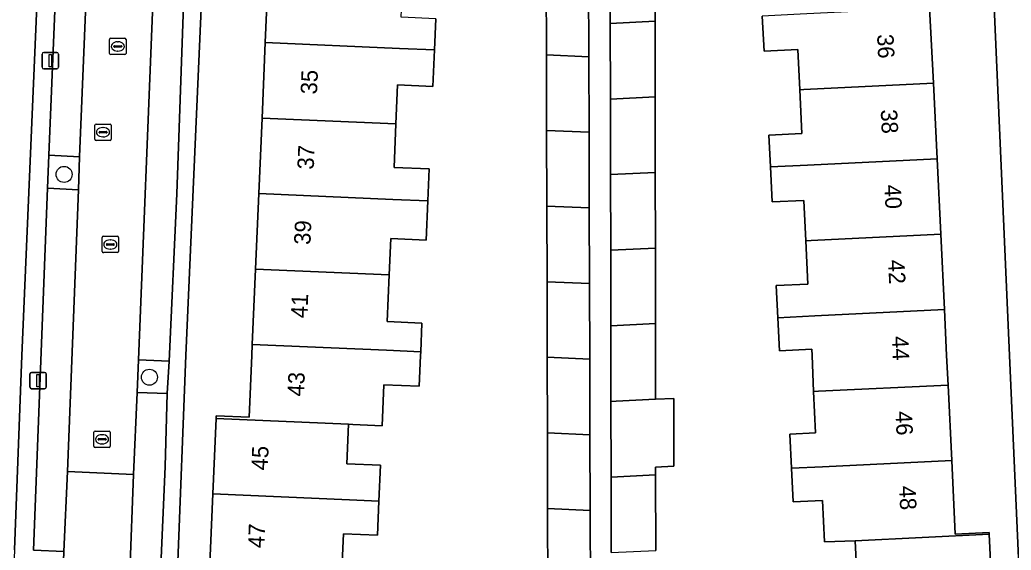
# Model space of a CAD drawing. Extents: x 162250 to 162661, y 380743 to 381606.
# Drawn here: x 162336.5 to 162396.8, y 380988.1 to 381020.5 of the extents above; entities that cross this region are included whole.
import ezdxf

# ---------------------------------------------------------------- set-up
doc = ezdxf.new("R2010")
doc.units = 0
for name, color, linetype in [('IMGEO_Boom', 7, 'Continuous'), ('IMGEO_Erf', 7, 'Continuous'), ('IMGEO_Groenvoorziening', 7, 'Continuous'), ('IMGEO_Kolk', 7, 'Continuous'), ('IMGEO_Lichtmast', 7, 'Continuous'), ('IMGEO_Pand', 7, 'Continuous'), ('IMGEO_Pand_nummerreeks', 7, 'Continuous'), ('IMGEO_Parkeervlak_open', 7, 'Continuous'), ('IMGEO_Rijbaan_lokaal_open', 7, 'Continuous'), ('IMGEO_Rioolput', 7, 'Continuous'), ('IMGEO_Voetpad_open', 7, 'Continuous')]:
    doc.layers.add(name, color=color, linetype=linetype)

msp = doc.modelspace()

# ---------------------------------------------------------------- linework, layer by layer
at = {"layer": 'IMGEO_Boom'}
for centre in [(162339.168, 381011.047), (162344.364, 380998.683)]:
    msp.add_circle(centre, 0.489, dxfattribs=at)
at = {"layer": 'IMGEO_Erf'}
for points in [[(162350.924, 381073.314), (162350.066, 381051.483), (162348.851, 381051.523), (162346.572, 381000), (162346.066, 380986.918)], [(162375.1, 381066.47), (162375.106, 381061.862), (162375.111, 381057.252), (162375.117, 381052.644), (162375.122, 381048.035), (162375.128, 381043.426), (162375.133, 381038.818), (162375.139, 381034.209), (162375.144, 381029.599), (162375.15, 381024.991), (162375.156, 381020.382), (162375.161, 381015.773), (162375.167, 381011.165), (162375.172, 381006.556), (162375.178, 381001.947), (162375.183, 380997.338), (162376.302, 380997.392), (162376.307, 380993.255), (162375.188, 380993.2), (162375.189, 380992.729), (162375.194, 380988.122)], [(162348.014, 380986.843), (162348.219, 380991.564), (162348.419, 380996.164), (162348.426, 380996.325), (162350.428, 380996.238), (162350.591, 381000), (162350.62, 381000.678), (162350.82, 381005.278), (162351.02, 381009.879), (162351.22, 381014.48), (162351.42, 381019.08), (162351.62, 381023.681), (162351.82, 381028.281), (162352.02, 381032.882), (162352.22, 381037.482), (162352.419, 381042.083), (162352.619, 381046.684), (162352.819, 381051.284), (162353.019, 381055.885), (162353.219, 381060.485), (162353.419, 381065.086)], [(162368.623, 380985.801), (162368.611, 380990.677), (162368.598, 380995.286), (162368.586, 380999.897), (162368.574, 381004.506), (162368.562, 381009.117), (162368.55, 381013.728), (162368.538, 381018.336), (162368.526, 381022.946), (162368.513, 381027.555), (162368.501, 381032.165), (162368.489, 381036.777), (162368.477, 381041.385), (162368.465, 381045.995), (162368.453, 381050.604), (162368.441, 381055.215), (162368.429, 381059.823), (162368.416, 381064.434)], [(162389.86, 381062.581), (162390.084, 381057.982), (162390.308, 381053.384), (162390.532, 381048.786), (162390.756, 381044.188), (162390.98, 381039.59), (162391.204, 381034.992), (162391.428, 381030.393), (162391.652, 381025.795), (162391.876, 381021.197), (162392.1, 381016.599), (162392.324, 381012.001), (162392.548, 381007.403), (162392.772, 381002.804), (162392.909, 381000), (162392.996, 380998.206), (162393.22, 380993.608), (162393.439, 380989.11), (162395.493, 380989.21), (162395.498, 380989.11), (162395.722, 380984.512)], [(162397.638, 380979.87), (162396.746, 381000), (162395.762, 381022.213), (162394.094, 381022.237), (162392.384, 381062.316)], [(162336.141, 380988.151), (162336.6, 381000), (162337.62, 381024.184), (162335.584, 381024.354)], [(162387.459, 380986.251), (162387.339, 380988.713), (162385.473, 380988.64), (162385.35, 380991.169), (162383.56, 380991.082), (162383.46, 380993.132), (162383.359, 380995.21), (162384.919, 380995.288), (162384.812, 380997.807), (162384.719, 381000), (162384.703, 381000.386), (162382.733, 381000.29), (162382.634, 381002.31), (162382.539, 381004.263), (162384.467, 381004.357), (162384.338, 381007.003), (162384.218, 381009.463), (162382.282, 381009.369), (162382.178, 381011.507), (162382.084, 381013.436), (162384.092, 381013.534), (162383.962, 381016.202), (162383.842, 381018.661), (162381.789, 381018.56), (162381.685, 381020.7)], [(162361.803, 381020.537), (162361.72, 381018.632), (162361.624, 381016.406), (162359.476, 381016.499), (162359.373, 381014.126), (162359.257, 381011.47), (162361.402, 381011.377), (162361.317, 381009.432), (162361.213, 381007.041), (162359.054, 381007.135), (162358.958, 381004.924), (162358.834, 381002.071), (162360.961, 381001.979), (162360.885, 381000.232), (162360.875, 381000), (162360.794, 380998.132), (162358.642, 380998.225), (162358.533, 380995.724), (162356.741, 380995.802), (162356.49, 380995.813), (162356.385, 380993.407), (162358.43, 380993.318), (162358.335, 380991.124), (162358.245, 380989.047), (162356.178, 380989.137), (162356.063, 380986.493)]]:
    msp.add_lwpolyline(points, dxfattribs=at)
at = {"layer": 'IMGEO_Groenvoorziening'}
for points in [[(162338.156, 381010.198), (162340.038, 381010.111), (162340.104, 381012.126), (162338.237, 381012.212)], [(162345.558, 380999.659), (162343.705, 380999.732), (162343.619, 380997.747), (162345.435, 380997.681)]]:
    msp.add_lwpolyline(points, close=True, dxfattribs=at)
at = {"layer": 'IMGEO_Kolk'}
for p, q in [((162341.937, 381018.422), (162341.937, 381019.274)), ((162342.012, 381019.348), (162342.864, 381019.348)), ((162342.196, 381018.842), (162342.196, 381018.854)), ((162342.239, 381018.891), (162342.637, 381018.891)), ((162342.425, 381019.128), (162342.45, 381019.128)), ((162342.68, 381018.854), (162342.68, 381018.842)), ((162342.938, 381019.274), (162342.938, 381018.422)), ((162342.864, 381018.348), (162342.012, 381018.348)), ((162342.634, 381018.805), (162342.236, 381018.805)), ((162342.448, 381018.568), (162342.423, 381018.568)), ((162341.483, 381006.349), (162341.483, 381007.201)), ((162341.558, 381007.275), (162342.41, 381007.275)), ((162341.742, 381006.769), (162341.742, 381006.781)), ((162341.785, 381006.818), (162342.183, 381006.818)), ((162341.971, 381007.055), (162341.996, 381007.055)), ((162342.226, 381006.781), (162342.226, 381006.769)), ((162342.484, 381007.201), (162342.484, 381006.349)), ((162342.41, 381006.275), (162341.558, 381006.275)), ((162342.18, 381006.732), (162341.782, 381006.732)), ((162341.994, 381006.495), (162341.969, 381006.495)), ((162340.978, 380994.473), (162340.978, 380995.325)), ((162341.053, 380995.399), (162341.905, 380995.399)), ((162341.979, 380995.325), (162341.979, 380994.473)), ((162341.237, 380994.893), (162341.237, 380994.905)), ((162341.675, 380994.856), (162341.277, 380994.856)), ((162341.28, 380994.942), (162341.678, 380994.942)), ((162341.466, 380995.179), (162341.491, 380995.179)), ((162341.721, 380994.905), (162341.721, 380994.893)), ((162341.905, 380994.399), (162341.053, 380994.399)), ((162341.489, 380994.619), (162341.464, 380994.619))]:
    msp.add_line(p, q, dxfattribs=at)
for points in [[(162341.937, 381018.422), (162341.937, 381019.274)], [(162342.012, 381019.348), (162342.864, 381019.348)], [(162342.938, 381019.274), (162342.938, 381018.422)], [(162342.864, 381018.348), (162342.012, 381018.348)], [(162341.483, 381006.349), (162341.483, 381007.201)], [(162341.558, 381007.275), (162342.41, 381007.275)], [(162342.484, 381007.201), (162342.484, 381006.349)], [(162342.41, 381006.275), (162341.558, 381006.275)], [(162340.978, 380994.473), (162340.978, 380995.325)], [(162341.053, 380995.399), (162341.905, 380995.399)], [(162341.979, 380995.325), (162341.979, 380994.473)], [(162341.905, 380994.399), (162341.053, 380994.399)]]:
    msp.add_lwpolyline(points, dxfattribs=at)
for centre, radius, start, end in [((162342.014, 381019.272), 0.0765, 91.55205, 178.44795), ((162342.014, 381019.272), 0.0765, 91.55205, 178.44795), ((162342.236, 381018.851), 0.0403, 85.87752, 175.75265), ((162342.233, 381018.841), 0.0366, 178.93798, 274.71019), ((162342.637, 381018.848), 0.043, 264.86636, 352.45326), ((162342.641, 381018.853), 0.0386, 1.73085, 96.63898), ((162342.862, 381019.272), 0.0765, 1.55205, 88.44795), ((162342.862, 381019.272), 0.0765, 1.55205, 88.44795), ((162342.014, 381018.424), 0.0765, 181.55205, 268.44795), ((162342.014, 381018.424), 0.0765, 181.55205, 268.44795), ((162342.862, 381018.424), 0.0765, 271.55205, 358.44795), ((162342.862, 381018.424), 0.0765, 271.55205, 358.44795), ((162341.56, 381007.199), 0.0765, 91.55205, 178.44795), ((162341.56, 381007.199), 0.0765, 91.55205, 178.44795), ((162341.782, 381006.778), 0.0403, 85.87752, 175.75265), ((162341.779, 381006.768), 0.0366, 178.93798, 274.71019), ((162342.183, 381006.775), 0.043, 264.86636, 352.45326), ((162342.187, 381006.78), 0.0386, 1.73085, 96.63898), ((162342.408, 381007.199), 0.0765, 1.55205, 88.44795), ((162342.408, 381007.199), 0.0765, 1.55205, 88.44795), ((162341.56, 381006.351), 0.0765, 181.55205, 268.44795), ((162341.56, 381006.351), 0.0765, 181.55205, 268.44795), ((162342.408, 381006.351), 0.0765, 271.55205, 358.44795), ((162342.408, 381006.351), 0.0765, 271.55205, 358.44795), ((162341.055, 380995.323), 0.0765, 91.55205, 178.44795), ((162341.055, 380995.323), 0.0765, 91.55205, 178.44795), ((162341.903, 380995.323), 0.0765, 1.55205, 88.44795), ((162341.903, 380995.323), 0.0765, 1.55205, 88.44795), ((162341.277, 380994.902), 0.0403, 85.87752, 175.75265), ((162341.274, 380994.892), 0.0366, 178.93798, 274.71019), ((162341.678, 380994.899), 0.043, 264.86636, 352.45326), ((162341.682, 380994.904), 0.0386, 1.73085, 96.63898), ((162341.055, 380994.475), 0.0765, 181.55205, 268.44795), ((162341.055, 380994.475), 0.0765, 181.55205, 268.44795), ((162341.903, 380994.475), 0.0765, 271.55205, 358.44795), ((162341.903, 380994.475), 0.0765, 271.55205, 358.44795)]:
    msp.add_arc(centre, radius, start, end, dxfattribs=at)
for centre, major_axis, ratio, start_param, end_param in [((162342.424, 381018.848), (-0.387, 0.002), 0.722429, 4.712389, 7.853982), ((162342.449, 381018.848), (-0.39, 0.002), 0.717154, 1.570796, 4.712389), ((162341.97, 381006.775), (-0.387, 0.002), 0.722429, 4.712389, 7.853982), ((162341.995, 381006.775), (-0.39, 0.002), 0.717154, 1.570796, 4.712389), ((162341.465, 380994.899), (-0.387, 0.002), 0.722429, 4.712389, 7.853982), ((162341.49, 380994.899), (-0.39, 0.002), 0.717154, 1.570796, 4.712389)]:
    msp.add_ellipse(centre, major_axis=major_axis, ratio=ratio, start_param=start_param, end_param=end_param, dxfattribs=at)
at = {"layer": 'IMGEO_Lichtmast'}
for p, q in [((162337.83, 381017.579), (162337.83, 381018.379)), ((162337.83, 381018.379), (162337.83, 381017.579)), ((162337.93, 381018.479), (162338.72, 381018.479)), ((162338.72, 381018.479), (162337.93, 381018.479)), ((162338.82, 381018.379), (162338.82, 381017.579)), ((162338.82, 381017.579), (162338.82, 381018.379)), ((162338.72, 381017.479), (162337.93, 381017.479)), ((162337.93, 381017.479), (162338.72, 381017.479)), ((162337.186, 380998.978), (162337.976, 380998.978)), ((162337.976, 380998.978), (162337.186, 380998.978)), ((162337.086, 380998.078), (162337.086, 380998.878)), ((162337.086, 380998.878), (162337.086, 380998.078)), ((162338.076, 380998.878), (162338.076, 380998.078)), ((162338.076, 380998.078), (162338.076, 380998.878)), ((162337.976, 380997.978), (162337.186, 380997.978)), ((162337.186, 380997.978), (162337.976, 380997.978))]:
    msp.add_line(p, q, dxfattribs=at)
for points in [[(162338.25, 381018.354), (162338.4, 381018.354), (162338.4, 381017.604), (162338.25, 381017.604), (162338.25, 381018.354)], [(162337.506, 380998.853), (162337.656, 380998.853), (162337.656, 380998.103), (162337.506, 380998.103), (162337.506, 380998.853)]]:
    msp.add_lwpolyline(points, dxfattribs=at)
for centre, start, end in [((162337.93, 381018.379), 90, 180), ((162337.93, 381018.379), 90, 180), ((162338.72, 381018.379), 0, 90), ((162338.72, 381018.379), 360, 90), ((162337.93, 381017.579), 180, 270), ((162337.93, 381017.579), 180, 270), ((162338.72, 381017.579), 270, 0), ((162338.72, 381017.579), 270, 0), ((162337.186, 380998.878), 90, 180), ((162337.186, 380998.878), 90, 180), ((162337.976, 380998.878), 0, 90), ((162337.976, 380998.878), 360, 90), ((162337.186, 380998.078), 180, 270), ((162337.186, 380998.078), 180, 270), ((162337.976, 380998.078), 270, 0), ((162337.976, 380998.078), 270, 0)]:
    msp.add_arc(centre, 0.1, start, end, dxfattribs=at)
at = {"layer": 'IMGEO_Pand'}
for points in [[(162372.421, 381024.858), (162372.429, 381020.249), (162375.156, 381020.382), (162375.15, 381024.991)], [(162359.808, 381023.325), (162351.62, 381023.681), (162351.42, 381019.08), (162359.589, 381018.725), (162361.72, 381018.632), (162361.803, 381020.537), (162359.691, 381020.629)], [(162371.111, 381022.833), (162368.526, 381022.946), (162368.538, 381018.336), (162371.124, 381018.223)], [(162383.962, 381016.202), (162384.222, 381016.215), (162392.1, 381016.599), (162391.876, 381021.197), (162383.998, 381020.813), (162381.685, 381020.7), (162381.789, 381018.56), (162383.842, 381018.661)], [(162372.436, 381015.641), (162375.161, 381015.773), (162375.156, 381020.382), (162372.429, 381020.249)], [(162361.72, 381018.632), (162359.589, 381018.725), (162351.42, 381019.08), (162351.22, 381014.48), (162359.373, 381014.126), (162359.476, 381016.499), (162361.624, 381016.406)], [(162371.124, 381018.223), (162368.538, 381018.336), (162368.55, 381013.728), (162371.137, 381013.616)], [(162383.962, 381016.202), (162384.092, 381013.534), (162382.084, 381013.436), (162382.178, 381011.507), (162384.446, 381011.617), (162392.324, 381012.001), (162392.1, 381016.599), (162384.222, 381016.215)], [(162372.443, 381011.032), (162375.167, 381011.165), (162375.161, 381015.773), (162372.436, 381015.641)], [(162351.02, 381009.879), (162359.19, 381009.524), (162361.317, 381009.432), (162361.402, 381011.377), (162359.257, 381011.47), (162359.373, 381014.126), (162351.22, 381014.48)], [(162371.137, 381013.616), (162368.55, 381013.728), (162368.562, 381009.117), (162371.15, 381009.004)], [(162384.338, 381007.003), (162384.67, 381007.019), (162392.548, 381007.403), (162392.324, 381012.001), (162384.446, 381011.617), (162382.178, 381011.507), (162382.282, 381009.369), (162384.218, 381009.463)], [(162372.443, 381011.032), (162372.451, 381006.423), (162375.172, 381006.556), (162375.167, 381011.165)], [(162351.02, 381009.879), (162350.82, 381005.278), (162358.958, 381004.924), (162359.054, 381007.135), (162361.213, 381007.041), (162361.317, 381009.432), (162359.19, 381009.524)], [(162371.15, 381009.004), (162368.562, 381009.117), (162368.574, 381004.506), (162371.163, 381004.393)], [(162384.338, 381007.003), (162384.467, 381004.357), (162382.539, 381004.263), (162382.634, 381002.31), (162384.893, 381002.42), (162392.772, 381002.804), (162392.548, 381007.403), (162384.67, 381007.019)], [(162372.458, 381001.814), (162375.178, 381001.947), (162375.172, 381006.556), (162372.451, 381006.423)], [(162350.62, 381000.678), (162358.791, 381000.323), (162360.885, 381000.232), (162360.961, 381001.979), (162358.834, 381002.071), (162358.958, 381004.924), (162350.82, 381005.278)], [(162371.163, 381004.393), (162368.574, 381004.506), (162368.586, 380999.897), (162371.175, 380999.785)], [(162392.996, 380998.206), (162392.909, 381000), (162392.772, 381002.804), (162384.893, 381002.42), (162382.634, 381002.31), (162382.733, 381000.29), (162384.703, 381000.386), (162384.719, 381000), (162384.812, 380997.807), (162385.117, 380997.822)], [(162372.458, 381001.814), (162372.466, 380997.205), (162372.782, 380997.221), (162375.183, 380997.338), (162375.178, 381001.947)], [(162358.642, 380998.225), (162360.794, 380998.132), (162360.875, 381000), (162360.885, 381000.232), (162358.791, 381000.323), (162350.62, 381000.678), (162350.591, 381000), (162350.428, 380996.238), (162348.426, 380996.325), (162348.419, 380996.164), (162356.49, 380995.813), (162356.741, 380995.802), (162358.533, 380995.724)], [(162371.175, 380999.785), (162368.586, 380999.897), (162368.598, 380995.286), (162371.188, 380995.174)], [(162393.22, 380993.608), (162392.996, 380998.206), (162385.117, 380997.822), (162384.812, 380997.807), (162384.919, 380995.288), (162383.359, 380995.21), (162383.46, 380993.132), (162385.341, 380993.224)], [(162375.183, 380997.338), (162372.782, 380997.221), (162372.466, 380997.205), (162372.473, 380992.597), (162375.189, 380992.729), (162375.188, 380993.2), (162376.307, 380993.255), (162376.302, 380997.392)], [(162356.49, 380995.813), (162348.419, 380996.164), (162348.219, 380991.564), (162356.541, 380991.202), (162358.335, 380991.124), (162358.43, 380993.318), (162356.385, 380993.407)], [(162371.188, 380995.174), (162368.598, 380995.286), (162368.611, 380990.677), (162371.201, 380990.564)], [(162393.22, 380993.608), (162385.341, 380993.224), (162383.46, 380993.132), (162383.56, 380991.082), (162385.35, 380991.169), (162385.473, 380988.64), (162387.339, 380988.713), (162395.498, 380989.11), (162395.493, 380989.21), (162393.439, 380989.11)], [(162372.473, 380992.597), (162372.48, 380987.99), (162375.194, 380988.122), (162375.189, 380992.729)], [(162358.335, 380991.124), (162356.541, 380991.202), (162348.219, 380991.564), (162348.014, 380986.843), (162353.01, 380986.626), (162356.063, 380986.493), (162356.178, 380989.137), (162358.245, 380989.047)], [(162371.201, 380990.564), (162368.611, 380990.677), (162368.623, 380985.801), (162371.215, 380985.688)], [(162387.339, 380988.713), (162387.459, 380986.251), (162385.581, 380986.159), (162385.685, 380984.024), (162387.397, 380984.107), (162395.722, 380984.512), (162395.498, 380989.11)]]:
    msp.add_lwpolyline(points, close=True, dxfattribs=at)
at = {"layer": 'IMGEO_Parkeervlak_open'}
for points in [[(162341.044, 381034.696), (162339.18, 381034.765), (162338.237, 381012.212), (162340.104, 381012.126)], [(162343.705, 380999.732), (162345.558, 380999.659), (162346.026, 381009.859), (162346.446, 381021.366), (162344.572, 381021.447)], [(162340.038, 381010.111), (162338.156, 381010.198), (162337.294, 380988.148), (162339.157, 380988.064), (162339.37, 380992.927)], [(162343.397, 380992.747), (162343.163, 380986.78), (162345.037, 380986.723), (162345.325, 380993.244), (162345.435, 380997.681), (162343.619, 380997.747)]]:
    msp.add_lwpolyline(points, close=True, dxfattribs=at)
at = {"layer": 'IMGEO_Rijbaan_lokaal_open'}
for points in [[(162339.37, 380992.927), (162343.397, 380992.747), (162343.619, 380997.747), (162343.705, 380999.732), (162344.572, 381021.447), (162344.666, 381023.38), (162345.223, 381036.984), (162341.181, 381037.079), (162341.163, 381036.688), (162341.044, 381034.696), (162340.104, 381012.126), (162340.038, 381010.111)], [(162339.157, 380988.064), (162339.119, 380986.868), (162343.163, 380986.78), (162343.397, 380992.747), (162339.37, 380992.927)]]:
    msp.add_lwpolyline(points, close=True, dxfattribs=at)
at = {"layer": 'IMGEO_Rioolput'}
for p, q in [((162341.037, 381013.19), (162341.037, 381014.042)), ((162341.112, 381014.116), (162341.964, 381014.116)), ((162342.038, 381014.042), (162342.038, 381013.19)), ((162341.296, 381013.61), (162341.296, 381013.622)), ((162341.734, 381013.573), (162341.336, 381013.573)), ((162341.339, 381013.659), (162341.737, 381013.659)), ((162341.525, 381013.896), (162341.55, 381013.896)), ((162341.78, 381013.622), (162341.78, 381013.61)), ((162341.964, 381013.116), (162341.112, 381013.116)), ((162341.548, 381013.336), (162341.523, 381013.336))]:
    msp.add_line(p, q, dxfattribs=at)
for points in [[(162341.037, 381013.19), (162341.037, 381014.042)], [(162341.112, 381014.116), (162341.964, 381014.116)], [(162342.038, 381014.042), (162342.038, 381013.19)], [(162341.964, 381013.116), (162341.112, 381013.116)]]:
    msp.add_lwpolyline(points, dxfattribs=at)
for centre, radius, start, end in [((162341.114, 381014.04), 0.0765, 91.55205, 178.44795), ((162341.114, 381014.04), 0.0765, 91.55205, 178.44795), ((162341.962, 381014.04), 0.0765, 1.55205, 88.44795), ((162341.962, 381014.04), 0.0765, 1.55205, 88.44795), ((162341.336, 381013.619), 0.0403, 85.87752, 175.75265), ((162341.333, 381013.609), 0.0366, 178.93798, 274.71019), ((162341.737, 381013.616), 0.043, 264.86636, 352.45326), ((162341.741, 381013.621), 0.0386, 1.73085, 96.63898), ((162341.114, 381013.192), 0.0765, 181.55205, 268.44795), ((162341.114, 381013.192), 0.0765, 181.55205, 268.44795), ((162341.962, 381013.192), 0.0765, 271.55205, 358.44795), ((162341.962, 381013.192), 0.0765, 271.55205, 358.44795)]:
    msp.add_arc(centre, radius, start, end, dxfattribs=at)
for centre, major_axis, ratio, start_param, end_param in [((162341.524, 381013.616), (-0.387, 0.002), 0.722429, 4.712389, 7.853982), ((162341.549, 381013.616), (-0.39, 0.002), 0.717154, 1.570796, 4.712389)]:
    msp.add_ellipse(centre, major_axis=major_axis, ratio=ratio, start_param=start_param, end_param=end_param, dxfattribs=at)
at = {"layer": 'IMGEO_Voetpad_open'}
for points in [[(162341.565, 381113.994), (162340.767, 381095.921), (162340.701, 381094.418), (162338.044, 381034.203), (162336.016, 381034.263), (162335.584, 381024.354), (162337.62, 381024.184), (162336.6, 381000), (162336.141, 380988.151), (162336.042, 380985.614), (162335.689, 380976.508), (162335.219, 380968.294), (162338.032, 380967.948)], [(162338.156, 381010.198), (162338.237, 381012.212), (162339.18, 381034.765), (162339.268, 381036.765), (162340.262, 381060.408), (162340.374, 381062.382), (162340.838, 381073.728), (162341.423, 381084.846), (162341.485, 381086.666), (162342.447, 381110.128)], [(162350.27, 381109.922), (162349.753, 381098.417), (162349.681, 381096.654), (162348.578, 381072.082), (162348.521, 381070.283), (162347.574, 381047.676), (162347.499, 381045.78), (162346.542, 381023.306), (162346.446, 381021.366), (162346.026, 381009.859), (162345.558, 380999.659), (162345.435, 380997.681), (162345.325, 380993.244), (162345.037, 380986.723), (162343.163, 380986.78), (162343.084, 380985.588), (162344.989, 380985.516), (162344.349, 380968.083), (162342.553, 380968.091)], [(162392.907, 381106.38), (162393.043, 381101.39), (162388.259, 381101.259), (162388.35, 381099.05), (162393.175, 381099.217), (162393.287, 381096.656), (162388.443, 381096.483), (162388.45, 381096.274), (162392.28, 381096.431), (162392.344, 381095.083), (162393.904, 381062.404), (162392.384, 381062.316), (162394.094, 381022.237), (162395.762, 381022.213), (162396.746, 381000), (162397.638, 380979.87)], [(162372.48, 380987.99), (162372.473, 380992.597), (162372.466, 380997.205), (162372.458, 381001.814), (162372.451, 381006.423), (162372.443, 381011.032), (162372.436, 381015.641), (162372.429, 381020.249), (162372.421, 381024.858), (162372.414, 381029.466), (162372.406, 381034.076), (162372.399, 381038.684), (162372.392, 381043.293), (162372.384, 381047.901), (162372.377, 381052.51), (162372.37, 381057.119), (162372.362, 381061.728), (162372.355, 381066.337)], [(162370.995, 381064.322), (162371.008, 381059.711), (162371.021, 381055.103), (162371.034, 381050.492), (162371.046, 381045.883), (162371.059, 381041.272), (162371.072, 381036.665), (162371.085, 381032.053), (162371.098, 381027.443), (162371.111, 381022.833), (162371.124, 381018.223), (162371.137, 381013.616), (162371.15, 381009.004), (162371.163, 381004.393), (162371.175, 380999.785), (162371.188, 380995.174), (162371.201, 380990.564), (162371.215, 380985.688)], [(162342.734, 380967.37), (162345.351, 380967.047), (162345.464, 380971.341), (162346.007, 380985.389), (162346.066, 380986.918), (162346.572, 381000), (162348.851, 381051.523)], [(162338.492, 380969.758), (162338.509, 380972.948), (162336.646, 380973.052), (162337.162, 380985.171), (162337.251, 380986.943), (162339.119, 380986.868), (162339.157, 380988.064), (162337.294, 380988.148), (162338.156, 381010.198)]]:
    msp.add_lwpolyline(points, dxfattribs=at)

# ---------------------------------------------------------------- texts
at = {"layer": 'IMGEO_Pand_nummerreeks'}
for s, rotation, p in [('36', 272.78882, (162388.672, 381019.577)), ('35', 87.51244, (162354.565, 381015.91)), ('38', 272.78882, (162388.895, 381014.989)), ('37', 87.51244, (162354.366, 381011.324)), ('40', 272.78882, (162389.118, 381010.404)), ('39', 87.51244, (162354.166, 381006.737)), ('42', 272.78882, (162389.341, 381005.825)), ('41', 87.51244, (162353.972, 381002.263)), ('44', 272.78906, (162389.569, 381001.172)), ('43', 87.49638, (162353.766, 380997.49)), ('46', 272.7863, (162389.791, 380996.598)), ('45', 87.51357, (162351.563, 380992.987)), ('48', 272.7863, (162390.013, 380992.047)), ('47', 87.51202, (162351.357, 380988.246))]:
    msp.add_text(s, height=1, rotation=rotation, dxfattribs=at).set_placement(p)

doc.saveas('drawing.dxf')
